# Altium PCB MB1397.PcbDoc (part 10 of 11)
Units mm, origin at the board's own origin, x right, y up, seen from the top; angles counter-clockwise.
Board outline 118.24 x 172.86 mm, 6 copper layers (Top Layer, L2_GND, L3_VCC, L4_SIG, L5_GND, Bottom Layer), stack 1.631 mm thick; 819 components, 632 nets, 2875 pads, 1523 vias.
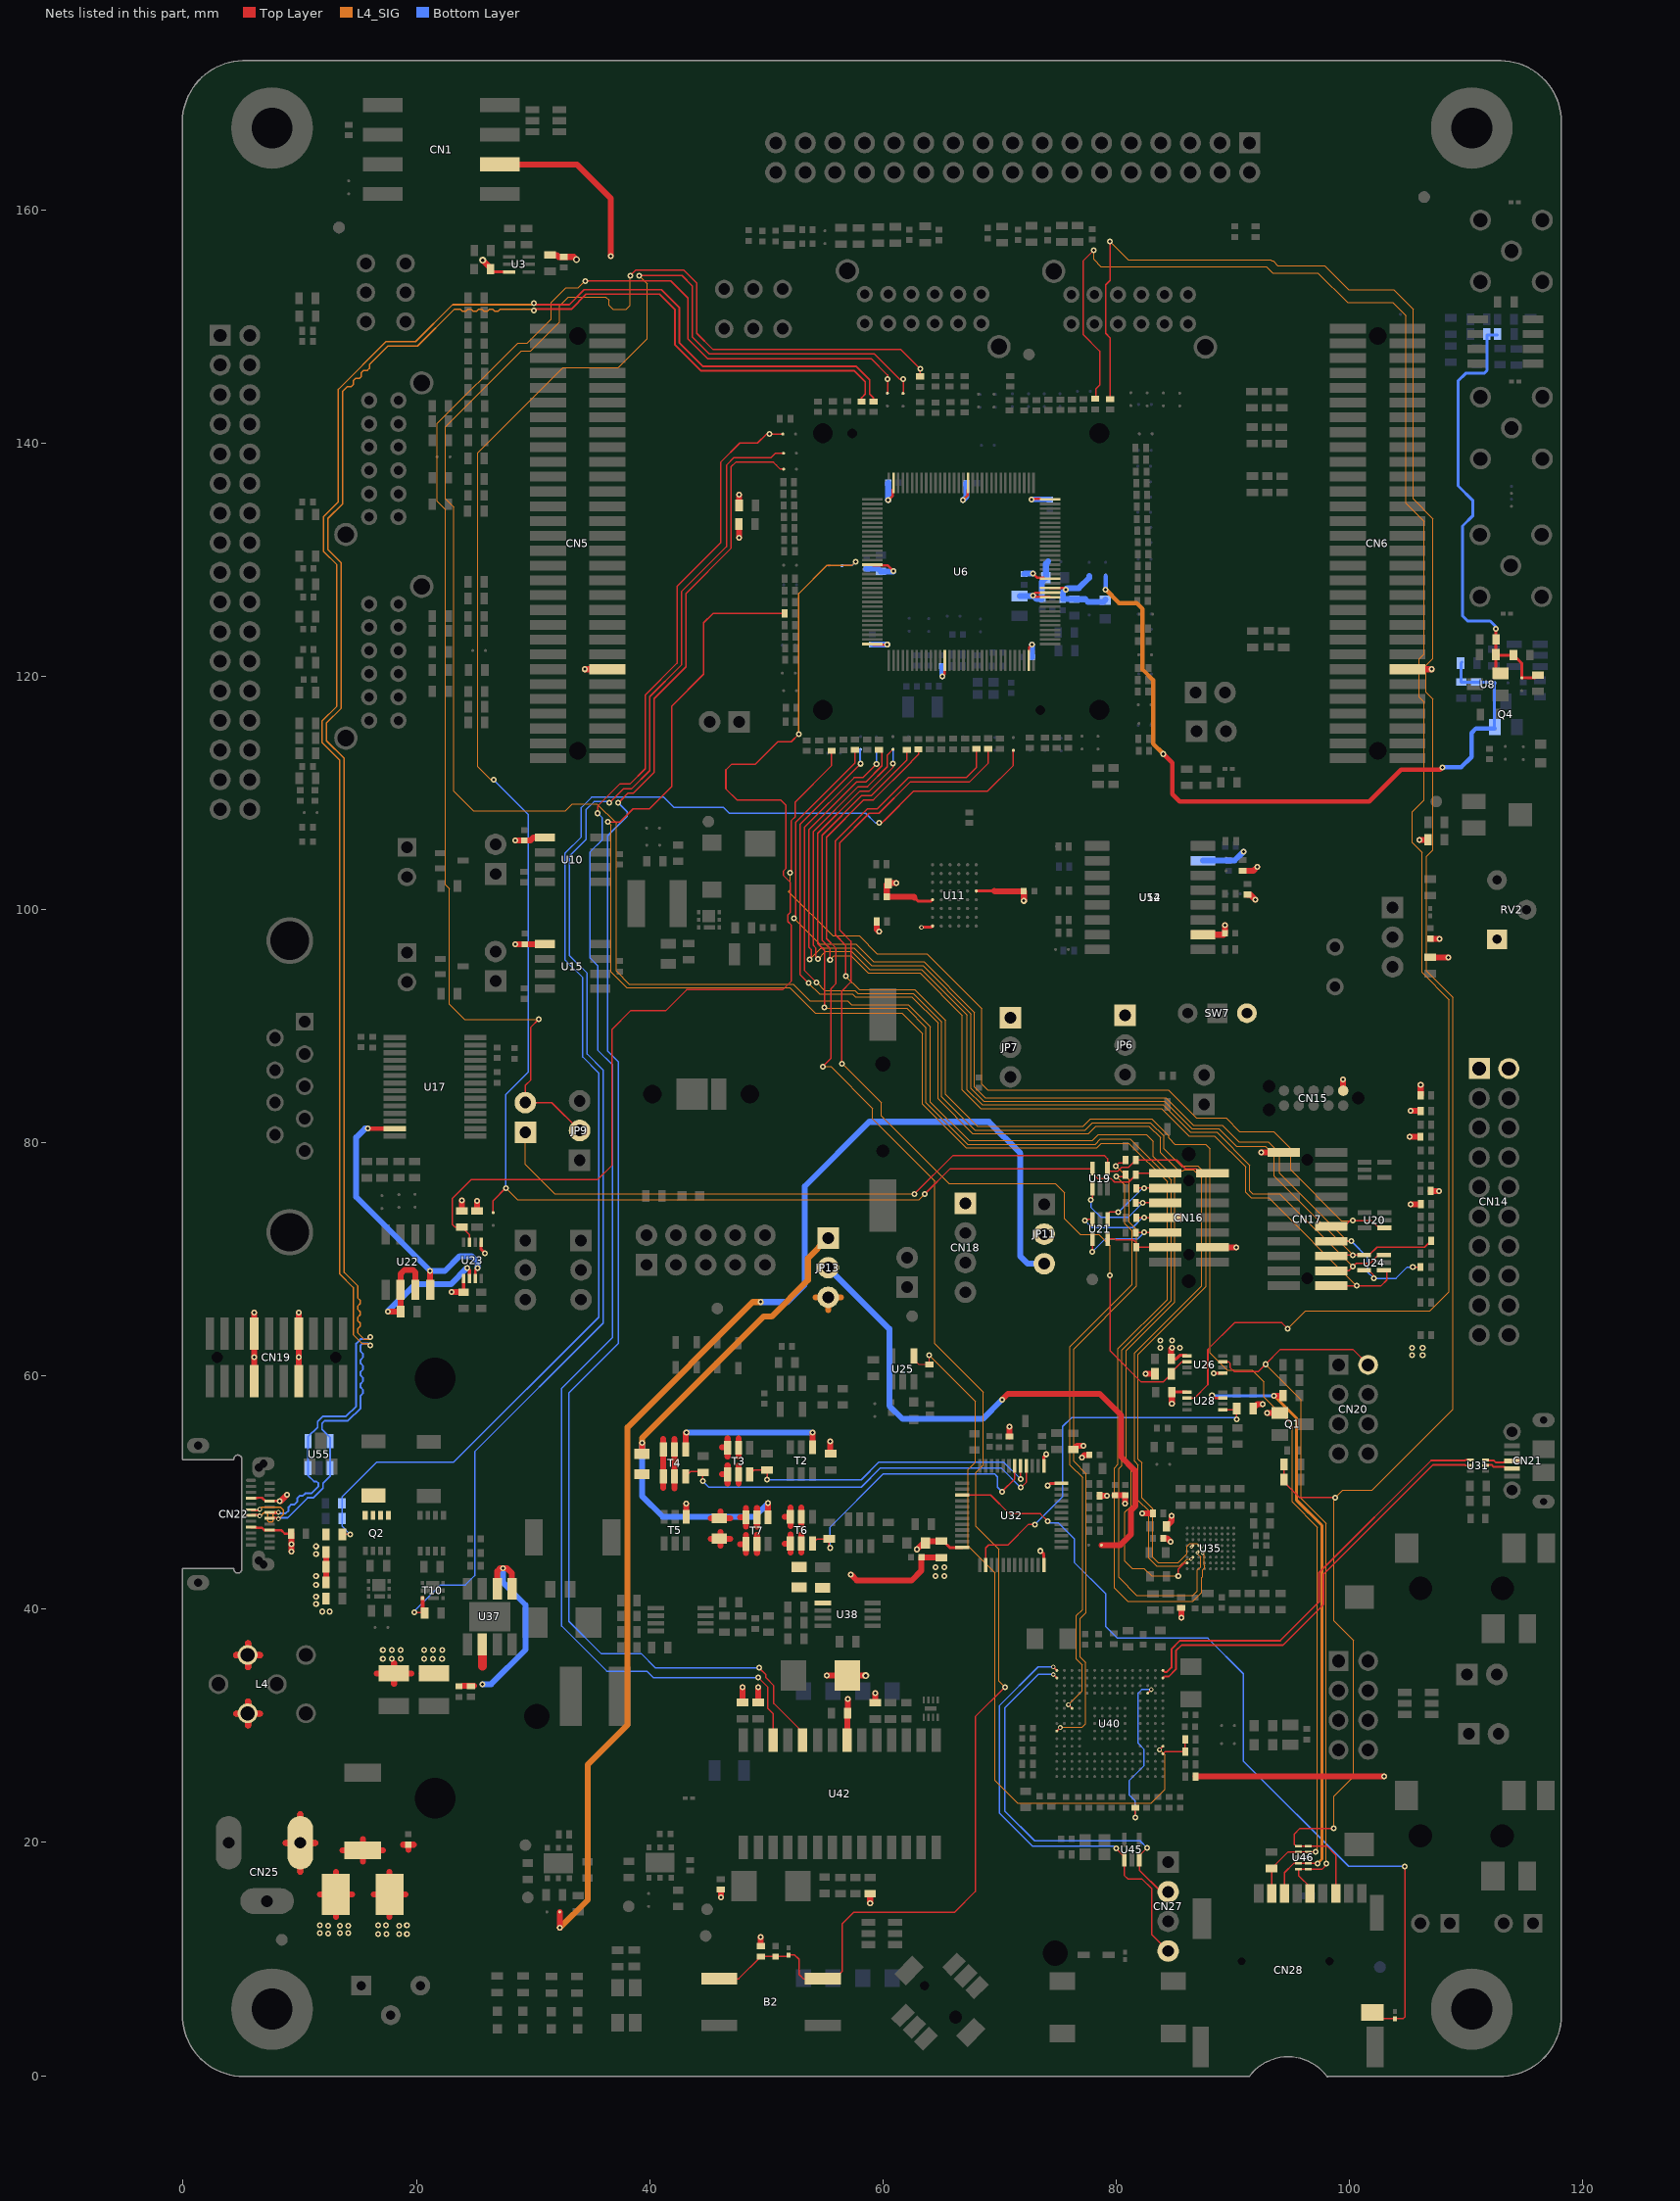
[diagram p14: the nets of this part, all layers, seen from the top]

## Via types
v1: diameter 0.508, hole 0.254, Top Layer to Bottom Layer, tented both sides, 1330 vias
v2: diameter 0.406, hole 0.203, Top Layer to Bottom Layer, tented both sides, 115 vias
v3: diameter 0.508, hole 0.254, Top Layer to Bottom Layer, 33 vias
v4: diameter 0.305, hole 0.152, Top Layer to Bottom Layer, tented both sides, 26 vias
v5: diameter 0.61, hole 0.305, Top Layer to Bottom Layer, tented both sides, 14 vias
v6: diameter 0.61, hole 0.33, Top Layer to Bottom Layer, tented both sides, 2 vias
v7: diameter 0.381, hole 0.203, Top Layer to Bottom Layer, tented both sides, 2 vias
v8: diameter 0.508, hole 0.203, Top Layer to Bottom Layer, tented both sides, 1 vias

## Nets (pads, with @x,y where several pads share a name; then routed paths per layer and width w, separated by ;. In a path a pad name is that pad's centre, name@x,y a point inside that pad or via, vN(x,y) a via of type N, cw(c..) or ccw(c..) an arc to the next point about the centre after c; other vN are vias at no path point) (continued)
RS485_DIR: R201.1 SB123.2 U23.3 | length 98.2
  Top Layer w0.127: U23.3@24.551,71.472 24.551,72.111 R201.1@23.897,72.765 23.312,72.765 23.086,72.991 23.086,75.232 24.689,76.835 35.535,76.835 36.779,78.08 36.779,89.738 38.354,91.313 41.366,91.313 43.17,93.116 51.41,93.116 52.154,93.861 52.154,98.658 51.841,98.971 51.841,99.531 52.07,99.76 52.07,102.311 51.482,102.9 51.482,103.315 51.692,103.525 51.692,108.93 51.224,109.398 47.475,109.398 46.533,110.34 46.533,111.969 47.035,112.471 49.073,112.471 50.978,114.376 52.139,114.376 52.799,115.037 v1(52.781,115.037)
  L4_SIG w0.127: v1(52.781,115.037) 52.781,127.089 55.205,129.513 57.364,129.513 v1(57.661,129.809)
  Bottom Layer w0.127: SB123.2@56.48,129.487 57.339,129.487 v1(57.661,129.809)
RS485_DIR_3V3: R213.2 U22.2 U22.3 U23.6 | length 16.4
  Top Layer w0.254: v1(24.356,69.263) 24.549,69.07 U23.6@24.549,68.656
  Top Layer w0.508: v1(17.546,65.532) R213.2@18.647,65.532 18.636,65.54 18.636,68.75 18.981,69.096 19.698,69.096 19.906,68.887 U22.3@19.907,67.391
  Bottom Layer w0.508: v1(17.546,65.532) 19.883,67.866 22.959,67.866 v1(24.356,69.263)
SAI_FS_A: SB107.1 U35.E3 | length 112.6
  Top Layer w0.127: v1(54.988,91.615) 54.988,96.492 54.399,97.081 54.399,106.523 58.034,110.157 58.834,110.157 60.858,112.179 v1(60.858,112.519) ; v4(86.951,44.84) U35.E3@87.077,44.966
  L4_SIG w0.102: v1(54.988,91.615) 55.077,91.526 62.037,91.526 63.701,89.863 63.701,83.434 67.254,79.88 78.202,79.88 78.633,80.312 81.197,80.312 84.706,76.803 84.706,66.469 80.465,62.227 80.465,52.296 80.236,52.067 80.236,42.72 81.76,41.196 86.586,41.196 86.967,41.577 86.967,43.355 87.236,43.623 87.236,44.486 86.951,44.771 v4(86.951,44.84)
  Bottom Layer w0.127: v1(60.858,112.519) SB107.1@60.858,113.724
SAI_MCLK_A: SB111.1 U35.D3 | length 110
  Top Layer w0.127: v1(54.303,93.749) 53.264,94.788 53.264,107.031 57.534,111.3 58.265,111.3 v1(59.446,112.481) ; U35.D3@87.077,45.466 v4(87.236,45.306)
  L4_SIG w0.102: v1(54.303,93.749) 54.988,93.063 57.579,93.063 57.833,92.809 62.598,92.809 65.047,90.361 65.047,83.944 67.892,81.1 77.34,81.1 77.97,81.73 82.928,81.73 84.097,80.561 84.097,79.499 85.653,77.943 85.71,77.999 86.994,77.999 87.729,77.264 87.729,67.696 81.887,61.854 81.887,52.88 82.192,52.575 82.192,49.546 83.128,48.61 83.128,44.452 83.586,43.993 85.319,43.993 86.078,44.752 86.078,45.391 86.328,45.641 86.898,45.641 v4(87.236,45.306)
  Bottom Layer w0.127: v1(59.446,112.481) 59.461,112.497 SB111.1@59.461,113.698
SAI_SCK_A: R30.1 U35.G1 | length 217.9
  Top Layer w0.127: v1(38.326,154.353) 38.783,154.81 42.949,154.81 44.041,153.718 44.041,149.4 45.438,148.003 61.554,148.003 v1(63.19,146.37) R30.1@63.19,145.713 ; v1(85.316,42.847) 85.316,43.434 85.847,43.965 U35.G1@86.077,43.966
  L4_SIG w0.102: v1(38.326,154.353) 38.326,151.813 37.97,151.458 36.853,151.458 36.497,151.813 36.497,152.245 36.243,152.499 33.017,152.499 32.281,151.762 32.281,150.391 29.792,147.902 29.004,147.902 22.502,141.399 22.502,135.202 23.213,134.49 23.213,110.157 24.889,108.481 32.789,108.481 33.373,109.065 35.481,109.065 37.132,107.414 37.132,94.714 38.25,93.596 52.296,93.596 53.744,92.149 56.97,92.149 57.287,91.831 62.164,91.831 64.072,89.924 64.072,83.495 67.381,80.185 77.95,80.185 78.458,80.693 82.575,80.693 83.157,80.111 83.157,78.831 85.011,76.977 85.011,66.342 80.871,62.202 80.871,52.372 81.277,51.966 81.277,48.842 80.744,48.308 80.744,44.117 81.379,43.482 82.395,43.482 83.03,42.847 v1(85.316,42.847)
SAI_SD_A: R98.2 U35.E4 | length 149.8
  Top Layer w0.127: v1(36.421,107.503) 37.45,107.503 38.58,108.633 39.977,108.633 41.907,110.564 41.907,117.455 44.625,120.172 44.625,124.584 45.415,125.374 R98.2@51.569,125.375 ; v4(87.417,44.806) U35.E4@87.577,44.966
  L4_SIG w0.102: v1(36.421,107.503) 36.421,107.49 36.675,107.236 36.675,94.663 38.047,93.292 52.017,93.292 54.201,91.107 61.646,91.107 63.396,89.357 63.396,83.309 67.13,79.576 78.329,79.576 78.715,79.962 81.069,79.962 84.376,76.655 84.376,66.571 80.16,62.354 80.16,52.423 79.855,52.118 79.855,41.831 80.998,40.688 86.586,40.688 87.348,41.45 87.348,42.72 87.417,42.789 87.417,43.372 87.562,43.517 87.562,43.749 87.541,43.77 87.541,44.612 87.417,44.736 v4(87.417,44.806)
SAI_SD_B: SB110.1 U35.F2 | length 108.2
  Top Layer w0.127: v1(53.617,93.698) 52.885,94.43 52.885,107.29 v1(58.09,112.494) ; v4(86.416,44.305) U35.F2@86.577,44.466
  L4_SIG w0.102: v1(53.617,93.698) 54.557,92.758 57.376,92.758 57.63,92.504 62.471,92.504 64.717,90.259 64.717,83.767 67.688,80.795 77.62,80.795 78.25,81.425 82.801,81.425 83.792,80.434 83.792,79.141 85.339,77.594 85.736,77.594 85.836,77.695 86.633,77.695 87.348,76.98 87.348,67.747 81.557,61.956 81.557,52.702 81.887,52.372 81.887,49.34 82.779,48.448 82.779,44.369 83.459,43.688 85.461,43.688 86.078,44.305 v4(86.416,44.305)
  Bottom Layer w0.127: SB110.1@58.039,113.673 58.039,112.545 v1(58.09,112.494)
SH0: R230.2 T4.3 U32.4 | length 33.4
  Top Layer w0.127: T4.3@43.076,51.389 43.485,51.798 44.549,51.798 v1(44.549,50.975) ; v1(71.816,50.429) 72.306,50.919 U32.4@72.307,52.292
  Bottom Layer w0.127: v1(44.549,50.975) 45.057,50.467 58.138,50.467 59.789,52.118 70.129,52.118 v1(71.816,50.429)
SH0_D: R227.2 T4.1 T4.2 T4.5 T4.6 | length 8.1
  Top Layer w0.508: 41.176,50.424 T4.1@41.176,51.389 T4.6@41.176,53.689 41.176,54.601 ; 42.126,50.38 T4.2@42.126,51.389 42.126,52.349 ; 42.126,52.636 T4.5@42.126,53.689 42.126,54.621
SH1: R229.2 T3.3 U32.5 | length 26.6
  Top Layer w0.127: T3.3@48.58,51.572 48.58,51.57 48.948,51.938 R229.2@50.069,51.94 v1(50.068,51.102) ; v1(71.806,51.151) U32.5@71.807,52.292
  Bottom Layer w0.127: v1(50.068,51.102) 58.138,51.102 59.662,52.626 70.33,52.626 v1(71.806,51.151)
SH1_D: R238.2 T3.1 T3.2 T3.5 T3.6 | length 9.4
  Top Layer w0.508: 45.245,47.785 R238.2@46.073,47.785 ; 46.073,48.39 R238.2@46.073,47.785 ; 46.203,51.57 T3.1@46.68,51.57 ; 46.203,53.871 T3.6@46.68,53.871 ; 46.68,50.792 T3.1@46.68,51.57 ; 46.68,52.349 T3.1@46.68,51.57 ; 46.68,53.094 T3.6@46.68,53.871 ; 46.68,54.648 T3.6@46.68,53.871 ; 46.901,47.785 R238.2@46.073,47.785 ; 47.63,50.792 47.63,52.349 ; 47.63,53.094 47.63,54.648
SH2: R242.2 T6.3 U32.6 | length 24.6
  Top Layer w0.127: T6.3@53.957,45.627 54.366,46.035 R242.2@55.39,46.036 55.39,45.342 v1(55.471,45.26) ; v1(70.203,50.086) 71.305,51.189 U32.6@71.307,52.292
  Bottom Layer w0.127: v1(55.471,45.26) 55.471,47.038 60.043,51.61 69.568,51.61 69.822,51.356 69.822,50.467 v1(70.203,50.086)
SH2_D: R252.2 T6.1 T6.2 T6.5 T6.6 | length 7.2
  Top Layer w0.508: 51.58,45.626 T6.1@52.057,45.627 ; 51.58,47.925 T6.6@52.057,47.927 ; 52.057,44.846 T6.1@52.057,45.627 ; 52.057,46.403 T6.1@52.057,45.627 ; 52.057,47.147 T6.6@52.057,47.927 ; 52.057,48.705 T6.6@52.057,47.927 ; 53.007,44.846 T6.2@53.007,45.627 53.007,46.403 ; 53.007,47.147 T6.5@53.007,47.927 53.007,48.705
SmartCard_CLK: SB15.1 U42.24 | length 137.1
  Top Layer w0.127: v1(37.31,109.141) 38.158,109.99 38.618,109.99 40.383,111.755 40.383,118.087 43.101,120.805 43.101,127.094 46.962,130.955 46.962,137.94 47.374,138.351 50.609,138.351 50.863,138.097 51.199,137.765 SB15.1@51.486,137.765 ; v1(49.375,34.973) 49.947,34.402 49.947,34.148 50.645,33.449 50.645,31.925 53.124,29.446 53.124,28.763 U42.24@53.123,28.765 ; SB15.1@51.486,137.763 SB15.1@51.486,137.763
  Bottom Layer w0.127: v1(37.31,109.141) 38.072,108.379 38.072,107.998 36.396,106.322 36.396,87.856 37.31,86.942 37.31,62.786 33.068,58.544 33.068,38.961 35.829,36.2 39.258,36.2 40.485,34.973 v1(49.375,34.973)
SmartCard_IO: SB12.1 U42.26 | length 138.8
  Top Layer w0.127: v1(35.532,108.252) 35.532,108.862 37.422,110.752 38.301,110.752 39.621,112.07 39.621,118.402 42.339,121.12 42.339,127.699 46.073,131.432 46.073,138.351 47.724,140.002 49.248,140.002 50.01,140.764 v1(50.264,140.764) SB12.1@51.415,140.764 ; v1(49.312,34.148) 50.137,33.322 50.137,31.483 50.584,31.036 50.584,28.763 U42.26@50.583,28.765
  Bottom Layer w0.127: v1(35.532,108.252) 35.938,107.846 35.938,105.992 34.897,104.95 34.897,95.832 35.532,95.197 35.532,87.958 36.802,86.688 36.802,63.294 32.459,58.951 32.459,38.555 36.319,34.694 39.748,34.694 40.295,34.148 v1(49.312,34.148)
SOURCE_EN: R264.2 SB13.1 T10.3 | length 121.9
  Top Layer w0.127: v1(19.842,39.731) R264.2@20.709,39.731 ; v1(36.548,109.141) 37.777,110.371 38.461,110.371 40.002,111.912 40.002,118.245 42.72,120.962 42.72,127.251 46.581,131.112 46.581,138.097 47.216,138.732 50.386,138.732 50.772,139.118 SB13.1@51.474,139.119
  Top Layer w0.305: T10.3@20.533,40.963 20.533,39.906 R264.2@20.709,39.731
  Bottom Layer w0.127: v1(19.842,39.731) 19.842,39.858 22.07,42.085 24.196,42.085 24.991,42.88 24.991,53.515 36.015,64.539 36.015,86.23 34.643,87.602 34.643,94.536 33.119,96.06 33.119,104.569 34.544,105.994 34.544,108.557 35.23,109.243 36.446,109.243 v1(36.548,109.141)
SPI2_MISO: CN28.7 R35.2 R231.1 R233.1 U46.5 U46.6 | length 200.2
  Top Layer w0.127: v1(79.474,157.274) 79.474,153.947 79.093,153.566 79.093,149.4 79.477,149.017 R35.2@79.477,143.675 ; R231.1@94.398,52.426 94.397,50.886 95.705,49.578 v1(98.778,49.578) ; v1(98.651,21.206) 95.755,21.206 95.273,20.724 95.273,19.835 95.41,19.698 98.052,19.698 98.824,18.926 CN28.7@98.824,15.624
  L4_SIG w0.102: v1(79.474,157.274) 81.023,155.725 93.241,155.725 93.342,155.623 93.444,155.623 93.85,155.217 97.889,155.217 99.946,153.159 103.777,153.159 105.458,151.478 105.458,135.202 107.16,133.5 107.16,121.536 106.576,120.952 106.576,118.615 107.16,118.031 107.16,105.103 106.627,104.569 106.627,94.714 108.887,92.453 108.887,57.147 101.953,50.213 99.413,50.213 v1(98.778,49.578) 98.651,49.451 98.651,39.014 100.33,37.335 100.33,25.654 98.651,23.975 v1(98.651,21.206)
SPI2_MOSI: R36.2 U28.2 | length 158.4
  Top Layer w0.127: v1(78.077,156.525) 77.188,155.636 77.188,149.273 78.585,147.876 78.585,144.955 78.247,144.617 R36.2@78.247,143.675 ; U28.2@86.052,58.116 86.716,58.115 87.856,59.256 87.856,62.278 90.142,64.564 94.206,64.564 v1(94.714,64.056)
  L4_SIG w0.102: v1(78.077,156.525) 78.077,155.727 78.689,155.115 92.885,155.115 93.419,154.582 97.3,154.582 99.84,152.042 103.706,152.042 104.823,150.924 104.823,134.846 106.398,133.271 106.398,121.892 105.966,121.46 105.966,118.209 106.398,117.777 106.398,109.395 105.382,108.379 105.382,105.712 106.22,104.874 106.22,94.587 108.557,92.25 108.557,67.231 106.906,65.58 96.238,65.58 v1(94.714,64.056)
SPI2_SCK: R134.2 R218.1 U26.2 | length 85.4
  Top Layer w0.127: v1(56.487,86.789) 56.462,86.815 56.462,92.987 57.249,93.774 57.249,97.279 56.291,98.237 56.291,105.72 58.824,108.252 59.659,108.252 62.326,110.919 67.409,110.919 69.012,112.522 R134.2@69.012,113.774 ; v1(79.474,68.628) 79.474,62.151 82.141,59.484 84.01,59.484 R218.1@84.721,60.194 84.719,60.31 85.644,61.234 U26.2@86.051,61.235
  L4_SIG w0.102: v1(56.487,86.789) 59.847,83.429 59.847,82.319 65.664,76.502 74.775,76.502 75.552,75.725 75.552,73.495 76.916,72.133 78.509,72.133 79.474,71.168 v1(79.474,68.628)
SPI_MOSI_3V3: CN28.3 R220.1 U28.7 U46.2 U46.9 | length 54.1
  Top Layer w0.127: CN28.3@94.423,15.625 94.422,17.409 95.212,18.199 v1(97.254,18.199)
  Top Layer w0.229: v1(88.212,58.341) 88.438,58.115 U28.7@89.152,58.116
  Top Layer w0.508: v1(93.52,58.316) 94.31,58.316 R220.1@94.311,58.318
  L4_SIG w0.254: v1(93.52,58.316) 95.476,56.36 95.476,49.345 97.635,47.186 97.635,18.58 v1(97.254,18.199)
  Bottom Layer w0.254: v1(88.212,58.341) 88.237,58.316 v1(93.52,58.316)
SPI_MOSI_DIR: R222.1 U28.5 U32.26 | length 33.4
  Top Layer w0.127: U32.26@68.806,43.79 68.806,45.26 69.06,45.514 70.711,45.514 72.489,47.292 72.997,47.292 v1(73.022,47.267) ; U28.5@89.152,57.116 90.223,57.114 R222.1@90.331,57.222 v1(90.33,56.284)
  Bottom Layer w0.127: v1(73.022,47.267) 75.41,49.654 75.41,55.674 76.172,56.436 90.178,56.436 v1(90.33,56.284)
SPI_SCK_3V3: CN20.2 CN28.5 U26.7 U46.1 U46.10 | length 64.5
  Top Layer w0.127: U26.7@89.151,61.235 89.611,61.234 89.786,61.059 89.786,60.703 90.117,60.373 92.174,60.373 v1(92.809,61.008) 94.079,62.278 100.279,62.278 CN20.2@101.6,60.96 ; CN28.5@96.623,15.625 96.622,16.175 95.631,17.165 U46.10@95.632,17.699 97.633,17.699 98.016,18.082 v1(98.016,18.209)
  L4_SIG w0.102: v1(92.809,61.008) 95.857,57.96 95.857,49.502 98.016,47.343 v1(98.016,18.209)
STLK_SWCLK: CN27.2 U40.A14 U45.3 | length 33.5
  Top Layer w0.127: v2(74.601,34.405) U40.A14@74.903,34.103 ; v1(82.649,19.53) 81.986,18.867 81.986,17.632 83.844,15.774 CN27.2@84.455,15.774
  Bottom Layer w0.127: v2(74.601,34.405) 73.304,34.404 70.457,31.557 70.457,22.692 73.01,20.14 82.039,20.14 v1(82.649,19.53)
STLK_SWDIO: CN27.4 U40.A15 U45.1 | length 38.2
  Top Layer w0.127: v2(74.601,35.055) U40.A15@74.903,34.753 ; v1(80.007,19.479) 80.686,18.801 80.686,17.186 80.981,16.891 82.192,16.891 83.058,16.025 83.058,12.091 CN27.4@84.455,10.694
  Bottom Layer w0.127: v2(74.601,35.055) 73.307,35.055 70,31.747 70,22.502 72.819,19.682 79.804,19.682 v1(80.007,19.479)
STLK_VCP_RX: R194.2 U40.C10 | length 50.7
  Top Layer w0.127: v2(75.901,31.805) U40.C10@76.203,31.503 ; v1(80.01,77.102) 80.642,77.102 R194.2@80.8,77.261
  L4_SIG w0.102: v2@75.9,31.806 77.086,32.992 77.086,35.227 76.578,35.735 76.578,39.444 77.112,39.977 77.112,51.305 76.045,52.372 76.045,62.532 81.379,67.866 81.379,72.438 80.744,73.073 80.744,76.37 v1(80.01,77.102)
STLK_VCP_TX: R189.1 U40.A7 | length 55.5
  Top Layer w0.127: U40.A7@74.905,29.554 v2(75.207,29.856) ; v1(79.967,78.006) 80.241,78.28 80.551,78.28 R189.1@80.797,78.527
  L4_SIG w0.102: v2@75.202,29.848 75.209,29.855 75.245,29.893 77.086,29.893 77.391,30.198 77.391,35.43 76.909,35.913 76.909,39.218 77.417,39.726 77.417,51.61 76.35,52.677 76.35,62.304 81.76,67.714 81.76,72.565 81.125,73.2 81.125,76.848 v1(79.967,78.006)
T50_4: JP13.1 R227.1 T7.4 | length 43.3
  Top Layer w0.508: R227.1@39.342,53.376 v1(39.342,54.277) ; T7.4@50.15,47.887 v1(50.15,49.083)
  L4_SIG w0.508: v1(39.342,54.277) 39.342,54.68 49.76,65.098 50.442,65.098 53.566,68.222 53.566,70.086 JP13.1@55.304,71.826
  Bottom Layer w0.508: v1(39.342,54.277) 39.342,49.705 41.12,47.927 48.994,47.927 v1(50.15,49.083)
T50_6: R238.1 R252.1 R253.1 T7.1 T7.2 T7.5 T7.6 U38.5 | length 10
  Top Layer w0.508: 45.245,46.038 R238.1@46.073,46.038 ; 46.073,45.433 R238.1@46.073,46.038 ; 46.073,46.639 R238.1@46.073,46.038 ; 46.901,46.038 R238.1@46.073,46.038 ; 47.772,45.585 T7.1@48.25,45.585 ; 47.772,47.887 T7.6@48.25,47.887 ; 48.25,44.808 T7.1@48.25,45.585 ; 48.25,46.365 T7.1@48.25,45.585 ; 48.25,47.107 T7.6@48.25,47.887 ; 48.25,48.664 T7.6@48.25,47.887 ; 49.2,44.808 T7.2@49.2,45.585 49.2,46.365 ; 49.2,47.107 T7.5@49.2,47.885 49.2,48.664
T_JTDI_STDC: CN16.10 R199.1 U19.1 | length 9.5
  Top Layer w0.127: v1(77.823,75.095) 77.823,75.105 77.955,75.237 U19.1@77.956,76.077 ; R199.1@81.684,74.847 v1(82.268,74.846) CN16.10@84.194,74.847
  Bottom Layer w0.127: v1(77.823,75.095) 77.823,74.47 78.674,73.619 81.041,73.619 v1(82.268,74.846)
T_NRST_STDC: CN16.12 R196.1 U21.1 | length 7
  Top Layer w0.127: U21.1@79.263,73.446 79.263,73.878 79.449,74.064 v1(80.185,74.064) ; R196.1@81.723,76.077 81.763,76.116 v1(82.395,76.116) CN16.12@84.194,76.117
  Bottom Layer w0.127: v1(80.185,74.064) 80.211,74.064 82.263,76.116 v1(82.395,76.116)
T_PWR_EN: R217.2 U25.4 U40.R5 | length 61.7
  Top Layer w0.102: U25.4@62.649,61.682 62.649,61.412 63.068,60.993 R217.2@63.98,60.993 63.98,61.755 v1(63.965,61.77)
  Top Layer w0.127: v2(83.702,27.949) U40.R5@84.005,28.251
  L4_SIG w0.102: v1(63.965,61.77) 67.917,57.818 67.917,52.626 67.282,51.991 67.282,45.438 69.619,43.101 69.619,25.321 71.549,23.391 83.005,23.391 84.173,24.559 84.173,27.48 v2@83.703,27.95
T_PWR_EXT: R277.1 R279.2 U40.R4 | length 3.1
  Top Layer w0.127: U40.R4@84.005,27.602 84.181,27.777 R279.2@85.921,27.778 R277.1@85.921,28.851
T_SWCLK_STDC: CN16.6 R206.1 U21.4 | length 8.7
  Top Layer w0.127: v1(77.955,70.655) 77.963,70.66 U21.4@77.963,71.746 ; R206.1@81.7,72.286 81.719,72.306 v1(82.395,72.306) CN16.6@84.194,72.307
  Bottom Layer w0.127: v1(77.955,70.655) 79.047,71.745 81.834,71.745 v1(82.395,72.306)
T_SWDIO_IN: R285.1 U40.N12 | length 14.2
  Top Layer w0.127: v1(81.636,22.146) R285.1@81.636,22.999 ; U40.N12@82.705,32.803 U40.N12@82.747,32.845 ; U40.N12@82.705,32.803 v2(83.007,33.106)
  Bottom Layer w0.127: v1(81.636,22.146) 81.636,23.541 81.125,24.051 81.125,25.321 82.395,26.591 82.395,27.988 81.887,28.496 81.887,32.814 82.179,33.106 v2(83.007,33.106)
T_SWDIO_STDC: CN16.4 R208.1 U21.5 | length 5.5
  Top Layer w0.127: U21.5@79.263,71.746 79.913,71.746 79.98,71.679 81.458,71.679 81.73,71.407 R208.1@81.73,71.036 ; R208.1@81.705,71.029 81.713,71.037 CN16.4@84.194,71.037
T_SWO_STDC: CN16.8 R204.1 U21.3 | length 8.8
  Top Layer w0.127: v1(77.315,73.327) 77.432,73.444 U21.3@77.963,73.446 ; R204.1@81.723,73.577 v1(82.395,73.576) CN16.8@84.194,73.577
  Bottom Layer w0.127: v1(77.315,73.327) 77.912,72.73 81.417,72.73 82.263,73.576 v1(82.395,73.576)
TAMPER_KEY: B2.1 B2.2 C157.2 R141.1 R294.1 U50.1 | length 140.8
  Top Layer w0.127: B2.1@45.964,8.318 47.63,8.316 R294.1@49.53,10.218 51.775,10.216 51.911,10.354 U50.1@51.914,10.356 ; U50.1@51.913,10.353 U50.1@51.914,10.356 ; v1(54.836,86.535) 55.535,87.234 55.535,93.203 55.979,93.647 55.979,96.685 55.156,97.508 55.156,106.202 58.349,109.395 59.185,109.395 62.433,112.644 62.433,112.674 63.043,113.284 R141.1@63.043,113.717 ; v1(70.457,33.322) 67.917,30.782 67.917,15.796 66.139,14.018 57.503,14.018 56.487,13.002 56.487,8.938 55.865,8.316 53.172,8.316 52.804,8.684 52.804,9.975 52.423,10.356 U50.1@51.914,10.356
  L4_SIG w0.102: v1(54.836,86.535) 55.522,86.535 59.129,82.928 59.129,82.045 64.463,76.711 64.463,62.761 68.603,58.621 68.603,52.372 67.968,51.737 67.968,47.114 69.949,45.133 69.949,33.83 v1(70.457,33.322)
TRACECLK: CN17.12 R147.1 U20.1 | length 84.1
  Top Layer w0.127: v1(52.051,103.147) 52.051,103.031 52.128,103.109 52.128,107.603 52.469,107.943 52.469,109.205 55.601,112.337 R147.1@55.601,113.621 ; CN17.12@98.428,72.823 99.543,72.822 100.048,73.327 v1(100.302,73.327) 101.882,73.327 102.502,72.708 U20.1@103.243,72.708
  L4_SIG w0.102: v1(52.051,103.147) 52.051,101.708 51.89,101.547 55.7,97.737 57.96,97.737 59.484,96.213 63.778,96.213 68.476,91.514 68.476,85.011 68.969,84.519 84.463,84.519 86.865,82.116 89.431,82.116 90.574,80.973 93.499,80.973 94.971,79.501 94.971,77.673 99.317,73.327 v1(100.302,73.327)
TRACED0: CN17.14 R145.1 R210.1 U24.5 | length 91.8
  Top Layer w0.127: v1(52.372,99.235) 52.507,99.37 52.507,107.446 57.607,112.547 R145.1@57.607,113.672 ; CN17.14@98.428,71.553 v1(100.173,71.552) ; U24.5@101.511,69.068 101.641,69.068 102.08,68.628 v1(102.08,68.374) ; v1(105.43,69.342) R210.1@106.091,69.342
  L4_SIG w0.102: v1(52.372,99.235) 54.582,97.025 57.681,97.025 59.187,95.519 63.508,95.519 67.854,91.173 67.854,84.77 68.76,83.863 84.254,83.863 86.611,81.506 89.101,81.506 90.523,80.084 93.038,80.084 94.005,79.116 94.005,77.385 99.839,71.552 v1(100.173,71.552)
  Bottom Layer w0.127: v1(100.173,71.552) 101.572,70.152 101.572,68.882 v1(102.08,68.374) 103.985,68.374 104.953,69.342 v1(105.43,69.342)
TRACED1: CN17.16 R144.1 R207.1 U24.4 | length 93.1
  Top Layer w0.127: v1(53.718,95.73) 53.851,95.862 53.851,96.56 53.642,96.768 53.642,106.843 57.719,110.919 58.519,110.919 59.916,112.316 59.916,113.429 R144.1@59.665,113.681 ; CN17.16@98.428,70.283 98.514,70.368 v1(100.302,70.368) 101.684,70.368 102.357,71.041 106.441,71.041 R207.1@106.991,71.59
  L4_SIG w0.102: v1(53.718,95.73) 54.684,96.695 57.503,96.695 59.027,95.171 63.424,95.171 67.549,91.046 67.549,84.643 68.633,83.558 84.127,83.558 86.487,81.201 88.796,81.201 90.294,79.703 92.784,79.703 93.548,78.938 93.548,77.122 v1(100.302,70.368)
TRACED2: CN17.18 SB28.1 U24.3 | length 89.1
  Top Layer w0.127: v1(54.43,95.755) 54.229,95.956 54.229,96.716 54.021,96.925 54.021,106.683 57.876,110.538 58.677,110.538 60.373,112.235 60.373,113.238 SB28.1@60.858,113.724 ; CN17.18@98.428,69.013 99.924,69.012 v1(100.289,69.378) 100.556,69.644 101.754,69.644 102.478,70.368 U24.3@103.21,70.368
  L4_SIG w0.102: v1(54.43,95.755) 55.065,96.39 57.325,96.39 58.849,94.866 63.297,94.866 67.231,90.932 67.231,84.529 68.506,83.254 84.003,83.254 86.36,80.896 88.638,80.896 91.463,78.072 91.463,75.888 91.712,75.639 94.028,75.639 v1(100.289,69.378)
TRACED3: CN17.20 R142.1 U24.1 | length 89.7
  Top Layer w0.127: v1(55.458,95.692) 55.458,96.665 54.778,97.346 54.778,106.363 58.191,109.776 59.027,109.776 62.052,112.801 R142.1@62.052,113.705 ; CN17.20@98.428,67.743 v1(100.607,67.742) 102.718,67.742 103.21,68.237 U24.1@103.21,69.068
  L4_SIG w0.102: v1(55.458,95.692) 55.801,96.035 57.249,96.035 58.722,94.562 63.17,94.562 66.807,90.925 66.807,84.522 68.38,82.949 83.876,82.949 86.233,80.592 88.44,80.592 91.107,77.925 91.107,75.74 91.564,75.283 93.066,75.283 v1(100.607,67.742)
USART1_RX: JP9.2 JP10.2 SB3.1 | length 123.1
  Top Layer w0.127: v1(30.477,90.574) 29.817,89.913 29.817,85.392 29.337,84.912 JP10.2@29.337,83.439 31.605,83.439 JP9.2@33.995,81.05 ; v1(34.465,153.896) 41.806,153.896 43.279,152.423 43.279,148.923 44.961,147.241 58.976,147.241 60.394,145.824 v1(60.394,145.479) SB3.1@60.394,144.247
  L4_SIG w0.102: v1(30.477,90.574) 24.127,90.574 22.832,91.869 22.832,101.775 22.502,102.105 22.502,134.287 21.791,134.998 21.791,141.679 28.694,148.582 29.505,148.582 31.57,150.645 31.57,152.042 32.828,153.3 33.869,153.3 v1(34.465,153.896)
USART1_TX: CN16.14 R194.1 SB4.1 SB40.1 U19.5 | length 181.8
  Top Layer w0.127: SB40.1@26.579,74.012 26.579,75.042 v1(27.658,76.121) ; v1(39.088,154.353) 42.771,154.353 43.66,153.464 43.66,149.08 45.118,147.622 59.281,147.622 61.438,145.466 v1(61.74,145.466) SB4.1@61.74,144.234 ; v1(63.599,75.613) 65.763,77.777 U19.5@77.956,77.777 77.955,77.386 78.407,76.934 79.55,76.934 79.855,76.629 81.069,76.629 81.826,77.386 CN16.14@84.194,77.387
  L4_SIG w0.102: v1(26.612,111.122) 26.388,111.122 25.27,112.24 25.27,139.164 32.586,146.479 37.31,146.479 39.774,148.943 39.774,153.667 v1(39.088,154.353) ; v1(27.658,76.121) 28.674,75.105 63.091,75.105 v1(63.599,75.613)
  Bottom Layer w0.127: v1(26.612,111.122) 29.588,108.146 29.588,86.053 27.658,84.122 v1(27.658,76.121)
USART1_TX_3V3: U17.13 U22.4 U23.7 | length 25.6
  Top Layer w0.229: U23.7@25.051,68.372 25.049,69.068 v1(25.245,69.263)
  Top Layer w0.381: v1(15.847,81.211) U17.13@18.14,81.213
  Top Layer w0.508: U22.4@21.177,67.391 v1(21.176,69.004)
  Bottom Layer w0.508: v1(15.847,81.211) 15.593,81.211 14.831,80.449 14.831,75.352 v1(21.176,69.004) 22.446,69.004 23.721,70.279 24.737,70.279 25.245,69.771 v1(25.245,69.263)
USB_DEV_HS_CN_N: CN21.2 U31.5 | length 2.4
  Top Layer w0.155: U31.5@111.654,52.316 U31.5@111.654,52.316 111.722,52.382 112.197,52.382 112.377,52.205 113.297,52.205 113.431,52.07 CN21.2@113.938,52.071
USB_DEV_HS_CN_P: CN21.3 U31.6 | length 2.4
  Top Layer w0.155: U31.6@111.654,52.816 111.704,52.763 112.357,52.763 112.535,52.586 113.215,52.586 113.35,52.72 CN21.3@113.938,52.721
USB_DEV_HS_N: U31.2 U40.R14 | length 36.4
  Top Layer w0.155: U40.R14@84.005,34.103 84.139,34.237 84.511,34.237 85.115,34.841 85.115,36.423 85.614,36.922 94.286,36.922 97.765,40.4 97.765,42.977 107.163,52.376 109.917,52.376 109.976,52.316 U31.2@110.354,52.316
USB_DEV_HS_P: U31.1 U40.R15 | length 36.3
  Top Layer w0.155: U40.R15@84.005,34.753 84.139,34.618 84.353,34.618 84.734,34.999 84.734,36.581 85.456,37.303 94.068,37.303 97.384,40.619 97.384,43.135 107.006,52.757 109.917,52.757 109.976,52.816 U31.1@110.354,52.816
USB_DM: CN22.A7 CN22.B7 R46.1 U55.3 U55.4 | length 168.3
  Top Layer w0.155: CN22.B7@5.814,48.532 CN22.B7@5.816,48.534 5.875,48.473 6.477,48.473 v2(6.566,48.562) ; CN22.A7@7.414,47.782 7.475,47.843 8.077,47.843 v2(8.166,47.755) ; v1(30.071,152.004) 30.211,151.864 33.111,151.864 34.394,153.147 40.993,153.147 42.55,151.59 42.55,148.575 44.541,146.583 57.689,146.583 58.864,145.408 58.864,144.198 59.181,143.882 R46.1@59.181,143.549
  L4_SIG w0.13: v2(6.566,48.562) 6.744,48.74 8.359,48.74 8.588,48.511 8.588,48.136 8.207,47.755 v2(8.166,47.755) ; v1@16.038,62.647 15.898,62.786 15.339,62.786 14.577,63.548 14.577,67.582 13.434,68.725 13.434,112.794 11.91,114.318 11.91,116.157 13.18,117.427 13.18,129.558 12.037,130.701 12.037,133.683 13.307,134.953 13.307,144.605 17.391,148.689 19.931,148.689 23.106,151.864 29.931,151.864 v1(30.071,152.004)
  Bottom Layer w0.155: v2(8.166,47.755) 8.255,47.843 8.956,47.843 10.668,49.555 11.156,49.555 11.986,50.386 11.986,50.797 12.606,51.417 12.606,54.724 11.91,55.42 11.91,55.931 12.139,56.159 14.128,56.159 15.212,57.244 15.212,58.308 15.415,58.511 15.415,58.821 15.212,59.025 15.212,59.334 15.415,59.538 15.415,59.847 15.212,60.051 15.212,60.361 15.415,60.564 15.415,60.874 15.212,61.077 15.212,61.387 15.415,61.59 15.415,61.9 15.212,62.103 15.212,62.629 15.37,62.786 15.872,62.786 v1(16.038,62.621)
USB_DP: CN22.A6 CN22.B6 R45.1 U55.1 U55.6 | length 168.6
  Top Layer w0.155: CN22.B6@5.814,48.034 CN22.B6@5.816,48.034 5.875,48.092 6.477,48.092 v2(6.566,48.003) ; CN22.A6@7.415,48.282 7.475,48.224 8.077,48.224 v2(8.166,48.313) ; v1(30.071,151.343) 30.211,151.483 33.269,151.483 34.552,152.766 40.836,152.766 42.169,151.432 42.169,148.417 44.383,146.202 57.531,146.202 58.483,145.25 58.483,144.198 58.166,143.882 R45.1@58.166,143.549
  L4_SIG w0.13: v2(6.566,48.003) 6.652,48.003 6.949,48.301 7.107,48.301 7.236,48.171 7.236,47.6 7.366,47.47 7.617,47.47 7.722,47.574 7.722,48.209 7.871,48.359 8.12,48.359 v2(8.166,48.313) ; v1@16.038,63.307 15.898,63.167 15.497,63.167 14.958,63.706 14.958,64.038 15.187,64.267 15.187,64.526 14.958,64.755 14.958,65.014 15.187,65.242 15.187,65.502 14.958,65.73 14.958,65.989 15.187,66.218 15.187,66.477 14.958,66.705 14.958,67.739 13.815,68.882 13.815,112.951 12.291,114.475 12.291,115.999 13.561,117.269 13.561,129.715 12.418,130.858 12.418,133.525 13.688,134.795 13.688,144.447 14.074,144.833 14.404,144.833 14.587,145.016 14.587,145.346 14.77,145.532 15.1,145.532 15.286,145.715 15.286,146.045 15.469,146.228 15.799,146.228 15.982,146.411 15.982,146.741 17.549,148.308 20.089,148.308 23.264,151.483 23.757,151.483 23.96,151.28 24.219,151.28 24.422,151.483 24.681,151.483 24.884,151.28 25.143,151.28 25.347,151.483 25.606,151.483 25.809,151.28 26.068,151.28 26.271,151.483 26.53,151.483 26.733,151.28 26.993,151.28 27.196,151.483 29.931,151.483 v1(30.071,151.343)
  Bottom Layer w0.155: v2(8.166,48.313) 8.255,48.224 8.796,48.224 9.035,48.463 9.035,48.76 9.256,48.981 9.549,48.981 9.774,49.203 9.774,49.5 9.992,49.718 10.246,49.718 10.465,49.936 10.998,49.936 11.605,50.543 11.605,50.795 11.45,50.95 11.224,50.95 10.706,51.468 U55.1@10.706,54.724 ; U55.1@10.706,54.411 10.706,54.778 11.529,55.601 11.529,56.089 11.981,56.54 13.97,56.54 14.831,57.401 14.831,62.787 15.212,63.167 15.872,63.167 v1(16.038,63.332)
uSD_CS: CN28.2 R135.2 R287.1 U46.4 U46.7 | length 141.9
  Top Layer w0.127: v1(56.805,94.282) 56.805,96.937 55.913,97.828 55.913,105.88 58.666,108.633 59.501,108.633 62.168,111.3 67.13,111.3 68.016,112.187 R135.2@68.016,113.765 ; CN28.2@93.323,15.625 R287.1@93.323,17.776 94.745,19.197 v1(97.099,19.197)
  L4_SIG w0.102: v1(56.805,94.282) 57.973,93.114 62.725,93.114 65.352,90.488 65.352,84.148 68.095,81.404 77.163,81.404 77.793,82.034 83.053,82.034 84.529,80.559 84.529,80.388 85.037,79.88 87.653,79.88 88.034,79.499 88.034,61.973 89.507,60.5 91.666,60.5 92.682,59.484 92.682,58.214 95.095,55.801 95.095,49.187 97.254,47.028 97.254,19.352 v1(97.099,19.197)
uSD_Detect: CN28.10 U32.15 U52.1 | length 74.3
  Top Layer w0.127: U32.15@66.807,49.792 69.228,49.792 70.838,48.181 73.505,48.181 v1(74.14,47.546) ; CN28.10@101.973,5.425 102.502,4.895 U52.1@103.886,4.895 ; U52.1@103.886,4.892 U52.1@103.886,4.895 ; v1(104.747,17.955) 104.747,5.039 104.6,4.895 U52.1@103.886,4.895
  Bottom Layer w0.127: v1(74.14,47.546) 74.267,47.419 75.029,47.419 76.426,46.022 76.426,43.99 79.093,41.323 79.093,38.529 80.109,37.513 87.856,37.513 90.904,34.465 90.904,26.972 99.921,17.955 v1(104.747,17.955)
VBUS: CN19.7 CN19.8 CN19.13 CN19.14 CN22.A4 CN22.A9 CN22.B4 CN22.B9 D8.1 Q2.5 Q2.6 Q2.7 Q2.8 R244.2 R246.2 R250.2 R254.2 R259.2 U36.1 | length 23
  Top Layer w0.203: CN22.B4@5.814,47.033 6.251,47.033 6.286,46.998 6.744,46.998 6.957,46.782 7.414,46.782 7.417,46.784 8.411,46.784 8.713,46.482 U36.1@9.281,46.482 ; CN22.B9@5.816,49.534 6.358,49.533 6.388,49.563 6.746,49.563 6.774,49.533 6.784,49.533 6.888,49.428 6.916,49.428 7.061,49.284 v1(8.268,49.284) v1@8.377,49.284
  Top Layer w0.508: CN19.7@6.096,59.56 CN19.7@6.096,59.56 v1(6.096,61.615) CN19.8@6.096,63.63 v1(6.096,65.453) ; v1@8.377,49.284 v1(8.9,49.807) ; v1(9.281,44.955) v1(9.281,45.593) U36.1@9.281,46.482 ; CN19.13@9.906,59.56 CN19.13@9.906,59.56 v1(9.906,61.615) CN19.14@9.906,63.63 v1(9.906,65.453) ; R254.2@12.254,42.306 R250.2@12.254,43.634 R246.2@12.254,44.904
  other v1: 11.91,39.799 12.545,39.799 11.402,40.434 11.402,41.069 11.402,42.085 11.402,42.847 11.402,44.752 11.402,45.387
VCP_RX_STDC: CN16.13 JP10.1 R189.2 U19.4 | length 66
  Top Layer w0.127: v1(62.71,75.613) 66.012,78.915 78.966,78.915 79.256,78.626 U19.4@79.256,77.777 79.484,77.546 80.137,77.546 80.49,77.899 81.069,77.899 R189.2@81.697,78.527 85.197,78.527 85.951,77.772 86.84,77.772 87.226,77.386 CN16.13@88.258,77.387
  L4_SIG w0.102: JP10.1@29.337,80.899 29.337,78.125 31.849,75.613 v1(62.71,75.613)
VDD: C13.1 C40.1 C46.2 C47.1 C48.1 C50.1 C51.2 C52.1 C61.1 C64.1 C69.1 C75.2 C80.2 C82.1 C83.2 C92.2 C94.1 C98.2 C121.1 C127.2 C184.2 CN1.5 CN5.48 CN6.48 CN14.1 CN14.2 CN15.1 CN16.3 CN17.1 CN18.1 JP7.1 JP11.2 Q1.1 R14.2 R16.2 R73.2 R80.2 R158.2 R161.1 R166.1 R171.2 R179.2 R183.2 R184.2 R186.2 R197.2 R200.2 R201.2 R202.2 R218.2 R222.2 R225.2 R228.2 R235.1 R237.1 R245.2 R261.1 R273.2 R274.2 R275.2 R282.2 R290.2 R291.2 R294.2 RV2.1 SW7.2 T5.4 U3.3 U10.5 U11.A6 U11.D6 U11.E1 U12.2 U15.5 U23.1 U23.5 U26.1 U26.5 U28.1 U35.D2 U42.21 U54.2 | length 128.2
  Top Layer w0.229: v4(86.451,45.34) 86.452,45.34 U35.D2@86.577,45.466
  Top Layer w0.254: U23.1@25.551,71.472 25.55,70.863 v1(25.88,70.533) ; C13.1@26.351,154.897 26.577,154.671 U3.3@27.932,154.671 ; 62.71,101.013 63.015,100.708 64.125,100.708 U11.D6@64.249,100.835 U11.D6@64.249,100.835 ; v2(63.294,98.473) 64.14,98.473 U11.A6@64.249,98.585 ; U11.E1@67.999,101.585 68.026,101.613 69.555,101.613 ; C64.1@84.721,61.464 85.136,61.463 85.443,61.77 86.015,61.77 U26.1@86.051,61.735 ; C69.1@84.771,58.619 86.048,58.618 U28.1@86.052,58.616 U28.1@86.052,58.616 ; U28.1@86.052,58.616 U28.1@86.053,58.616 ; v1(88.364,60.234) U26.5@89.151,60.235
  Top Layer w0.305: C61.1@24.039,67.187 24.051,67.198 U23.5@24.051,68.123
  Top Layer w0.508: v1(23.005,67.186) C61.1@24.039,67.187 ; R201.2@23.896,74.165 v1(23.896,75.057) ; R202.2@25.199,74.165 v1(25.199,75.024) ; v5(25.679,155.677) 26.351,155.005 C13.1@26.351,154.897 ; CN1.5@27.135,163.889 33.744,163.888 36.675,160.957 v1(36.675,156.004) ; v1(28.473,105.913) 29.764,105.913 30.02,106.169 U10.5@31.011,106.171 ; v1(28.478,97.008) 29.309,97.008 29.329,97.028 U15.5@31.011,97.029 ; R14.2@31.445,156.123 32.03,156.123 32.193,155.96 R16.2@32.639,155.96 33.491,155.96 v5(33.723,155.727) ; v1(34.44,120.599) CN5.48@36.385,120.601 ; T5.4@43.134,47.912 v1(43.134,49.07) ; v1(46.104,15.288) R291.2@46.103,15.952 ; v1(47.658,131.874) R80.2@47.658,133.144 ; R73.2@47.658,134.668 v1(47.658,135.557) ; R273.2@47.974,32.012 v1(47.973,33.317) ; R274.2@49.313,32.012 49.314,32.012 v1(49.314,33.322) ; R294.2@49.53,11.118 v1(49.53,11.887) ; v1(55.178,34.313) C121.1@56.936,34.313 v5(58.529,34.313) ; R228.2@55.491,53.327 v1(55.491,54.384) ; U42.21@56.933,28.765 56.934,28.763 56.934,31.044 C127.2@56.975,31.087 ; v1(56.975,32.306) C127.2@56.975,31.087 ; C127.2@56.977,31.088 C127.2@56.975,31.087 ; v1(57.249,42.974) 57.757,42.466 62.456,42.466 63.307,43.317 C98.2@63.308,44.455 R245.2@64.976,44.455 ; v1(58.9,14.808) R290.2@58.9,15.599 R290.2@58.9,15.603 ; R275.2@59.336,31.987 v1(59.337,32.814) ; R171.2@59.467,98.982 59.466,98.288 v1(59.662,98.092) ; C48.1@60.326,101.088 C48.1@60.328,101.087 ; C46.2@60.455,102.255 C46.2@60.455,102.258 ; C46.2@60.457,102.256 C46.2@60.328,102.126 ; v1(61.161,102.258) C46.2@60.455,102.258 ; 62.71,101.013 62.636,101.087 C48.1@60.328,101.087 ; 69.555,101.613 69.596,101.572 72.085,101.572 v1(72.085,100.736) ; R225.2@70.845,54.803 v1(70.846,55.667) ; C75.2@76.313,53.695 76.642,54.023 v1(77.188,54.023) ; v1(77.061,53.007) 77.29,53.236 C80.2@77.679,53.238 ; R235.1@78.588,49.725 78.588,49.726 v1(79.2,49.726) ; C82.1@79.855,49.764 80.744,49.764 v1(80.744,49.07) ; v1(82.245,48.205) 83.128,48.205 R237.1@83.147,48.225 ; v1(82.522,60.193) R218.2@83.321,60.194 ; C94.1@84.047,46.077 84.379,46.076 v1(84.658,45.796) ; C92.2@84.297,47.119 84.757,47.579 v1(84.757,48.003) ; C64.1@84.721,61.464 84.719,62.316 v1(84.808,62.405) ; v1(84.77,57.643) C69.1@84.771,58.619 ; v1(85.57,39.291) R261.1@85.57,40.112 ; R282.2@86.821,25.656 v1(102.969,25.654) ; U12.2@87.454,97.839 89.182,97.838 C51.2@89.312,97.966 v1(89.311,98.671) ; CN16.3@88.258,71.037 90.273,71.037 v1(90.274,71.036) ; R161.1@90.839,103.333 90.838,103.335 91.775,103.335 v1(92.098,103.655) ; R166.1@91.26,101.278 91.498,101.277 v1(91.945,100.833) ; R222.2@91.731,57.222 92.088,57.579 v1(92.555,57.579) ; v1(92.426,79.172) CN17.1@94.358,79.173 ; v1(92.936,56.83) Q1.1@94.023,56.83 ; CN15.1@99.464,84.463 v1(99.464,85.443) ; CN6.48@104.965,120.601 v1(107.058,120.599) ; v1(105.176,80.518) R186.2@106.091,80.518 ; v1(105.255,74.724) R200.2@106.075,74.724 ; v1(105.255,82.725) R184.2@106.075,82.725 ; v1(106.002,105.982) R158.2@106.742,105.983 ; R183.2@106.103,84.074 v1(106.103,84.971) ; R179.2@106.934,95.902 v1(108.463,95.9) ; C50.1@106.934,97.498 v1(107.709,97.498) ; R197.2@106.975,75.867 R197.2@106.978,75.867 v1(107.668,75.867) ; C48.1@60.328,101.087 C46.2@60.328,102.126 ; C46.2@60.328,102.126 60.328,102.128 C46.2@60.455,102.258
  Bottom Layer w0.508: U54.2@87.454,104.189 87.475,104.211 C184.2@89.644,104.211 ; C184.2@89.645,104.21 C184.2@89.644,104.211 ; v1(90.904,104.95) 90.165,104.211 C184.2@89.644,104.211
  other v1: 105.382,61.77 106.271,61.77 83.792,62.405 85.443,62.405 105.382,62.405 106.271,62.405 83.792,63.04 84.808,63.04
VDD1: JP13.3 L3.1 R245.1 T2.4 T4.4 U32.1 U32.24 U32.36 U32.48 | length 25
  Top Layer w0.229: 74.336,50.79 U32.48@75.307,50.792
  Top Layer w0.254: R245.1@64.996,45.832 65.187,45.832 65.728,45.291 U32.24@66.807,45.292 ; v1(73.505,45.006) 73.805,44.707 73.805,43.792 U32.36@73.807,43.79 ; U32.1@73.807,52.292 73.805,52.291 73.805,53.073 v1(74.013,53.282) ; v1(74.14,50.594) 74.336,50.79
  Top Layer w0.508: T4.4@43.076,53.691 43.076,55.09 v1(43.152,55.166) ; v1(53.947,55.166) 53.957,55.156 T2.4@53.957,53.871 ; v1(62.908,45.133) 63.466,45.691 L3.1@63.637,45.691 63.777,45.832 R245.1@64.996,45.832
  L4_SIG w0.508: 54.201,66.746 JP13.3@55.304,66.746 ; 55.303,65.641 JP13.3@55.304,66.746 ; 56.408,66.746 JP13.3@55.304,66.746
  Bottom Layer w0.508: v1(43.152,55.166) v1(53.947,55.166)
  other v1: 64.488,42.847 65.25,42.847 64.488,43.609 65.25,43.609
VDD_ADJ: JP11.3 SB48.2 | length 108.4
  Top Layer w0.508: v1(32.286,12.677) SB48.2@32.287,14.05
  L4_SIG w0.508: v1(32.286,12.677) 34.696,15.088 34.696,26.693 38.1,30.097 38.1,55.603 48.839,66.342 v1(49.502,66.342)
  Bottom Layer w0.508: v1(49.502,66.342) 51.788,66.342 53.312,67.866 53.312,76.274 58.834,81.795 69.078,81.795 71.776,79.097 71.776,70.259 72.413,69.622 JP11.3@73.83,69.622
VDD_MCU: C160.2 C161.2 C162.2 C163.1 C164.2 C165.2 C173.2 C175.2 C176.2 JP6.1 JP13.2 SB43.2 U6.13 U6.31 U6.47 U6.64 U6.79 U6.95 U6.111 U6.128 | length 69.8
  Top Layer w0.203: U6.111@59.083,129.566 59.137,129.511 60.405,129.511 v1(60.909,129.007) ; U6.128@59.083,122.766 59.134,122.715 v1(60.368,122.715) ; v1@60.454,135.097 60.848,135.491 U6.95@60.848,135.966 ; v1(65.1,120.002) 65.301,120.203 U6.13@65.301,120.929 ; v1(66.853,135.098) 67.246,135.491 U6.79@67.246,135.966 ; U6.31@72.528,122.149 72.528,122.475 v1(72.789,122.735) ; v1(72.743,135.166) 72.796,135.219 U6.64@73.49,135.219 ; v1(72.87,128.816) 73.246,128.44 U6.47@73.762,128.44
  Top Layer w0.508: v1(70.203,57.96) 70.711,58.468 78.585,58.468 80.422,56.631 80.422,53.075 81.633,51.864 81.633,48.842 81.252,48.461 81.252,46.403 80.35,45.502 SB43.2@78.74,45.502
  Bottom Layer w0.457: v1(72.743,135.166) C162.2@74.323,135.166
  Bottom Layer w0.508: JP13.2@55.304,69.286 60.551,64.038 60.551,57.452 61.694,56.309 68.552,56.309 v1(70.203,57.96) ; C164.2@58.603,129.216 59.593,129.215 C163.1@59.817,128.992 60.894,128.991 v1(60.909,129.007) ; C173.2@59.083,122.716 v1(60.368,122.715) ; v1(60.452,135.098) C160.2@60.453,136.586 ; v1(65.1,120.002) C175.2@65.1,120.886 ; v1(66.853,135.098) 67.153,135.397 C161.2@67.153,136.566 ; C165.2@72.108,128.77 72.154,128.816 v1(72.87,128.816) ; C176.2@72.789,121.638 v1(72.789,122.735)
VDDA: C167.1 C170.2 L9.2 SB85.1 SB90.2 U6.45 | length 8.8
  Top Layer w0.203: U6.45@74.323,127.566 75.529,127.564 v1(75.664,127.429)
  Bottom Layer w0.508: C170.2@75.41,126.609 C170.2@75.413,126.609 ; SB90.2@77.696,126.38 SB90.2@77.696,126.378 ; SB85.1@77.696,128.58 77.696,128.445 76.807,127.556 75.791,127.556 v1(75.664,127.429) 75.413,127.178 C170.2@75.413,126.609 ; L9.2@79.093,126.578 79.036,126.52 78.895,126.378 SB90.2@77.696,126.378 ; C170.2@75.413,126.609 76.421,126.609 76.426,126.604 77.346,126.604 77.569,126.378 SB90.2@77.696,126.378
VIN_EXT: C123.2 C124.2 C125.2 L4.2 R272.2 U37.1 U37.2 U37.6 | length 34.4
  Top Layer w0.508: 4.536,36.063 L4.2@5.565,36.063 ; 5.565,35.034 L4.2@5.565,36.063 ; 5.565,37.092 L4.2@5.565,36.063 ; 6.594,36.063 L4.2@5.565,36.063 ; 16.604,34.501 C124.2@18.082,34.501 ; 18.082,33.622 C124.2@18.082,34.501 ; 18.082,35.38 C124.2@18.082,34.501 ; 19.561,34.501 C124.2@18.082,34.501 ; C123.2@20.46,34.501 C123.2@21.938,34.501 ; 24.026,33.434 R272.2@24.943,33.434 ; U37.2@26.924,41.736 26.924,43.253 27.196,43.525 v1(27.432,43.525) 27.745,43.525 28.194,43.076 U37.1@28.194,41.736
  Top Layer w0.762: 25.654,35.111 U37.6@25.654,36.986 U37.6@25.654,36.995
  L4_SIG w0.508: 4.536,36.063 L4.2@5.565,36.063 ; 5.565,35.034 L4.2@5.565,36.063 ; 5.565,37.092 L4.2@5.565,36.063 ; 6.594,36.063 L4.2@5.565,36.063
  Bottom Layer w0.508: v1(25.668,33.576) 26.396,33.576 29.359,36.539 29.359,40.366 27.432,42.293 v1(27.432,43.525)
  other v1: 17.117,35.735 17.879,35.735 18.641,35.735 20.673,35.735 21.435,35.735 22.197,35.735 17.117,36.497 17.879,36.497 18.641,36.497 20.673,36.497 21.435,36.497 22.236,36.497
VIN_EXT_CONN: CN25.1 F1.1 | length 21.6
  Top Layer w0.508: 8.771,19.975 CN25.1@10.051,19.975 ; 10.051,17.498 CN25.1@10.051,19.975 ; 10.051,22.454 CN25.1@10.051,19.975 ; 11.328,19.975 CN25.1@10.051,19.975 ; 11.717,15.552 F1.1@13.097,15.554 ; 13.096,13.625 F1.1@13.097,15.554 ; 13.096,17.48 F1.1@13.097,15.554 ; 14.475,15.552 F1.1@13.097,15.554
  L4_SIG w0.508: 8.771,19.975 CN25.1@10.051,19.975 ; 10.051,17.498 CN25.1@10.051,19.975 ; 10.051,22.454 CN25.1@10.051,19.975 ; 11.328,19.975 CN25.1@10.051,19.975
  other v1: 12.443,12.189 13.459,12.215 14.171,12.215 11.732,12.24 12.443,12.85 13.459,12.875 14.171,12.875 11.732,12.901
VIN_EXT_UNFILT: C147.1 F1.2 L4.1 U43.1 | length 21.6
  Top Layer w0.508: 4.536,31.062 L4.1@5.565,31.062 ; 5.565,30.033 L4.1@5.565,31.062 ; 5.565,32.09 L4.1@5.565,31.062 ; 6.594,31.062 L4.1@5.565,31.062 ; 13.647,19.324 U43.1@15.397,19.324 ; 15.397,18.377 U43.1@15.397,19.324 ; 15.397,20.274 U43.1@15.397,19.324 ; 16.319,15.552 F1.2@17.697,15.554 ; 17.145,19.324 U43.1@15.397,19.324 ; 17.696,13.625 F1.2@17.697,15.554 ; 17.696,17.48 F1.2@17.697,15.554 ; 18.844,19.812 C147.1@19.304,19.813 ; 19.075,15.552 F1.2@17.697,15.554 ; 19.304,19.378 C147.1@19.304,19.813 ; 19.761,19.812 C147.1@19.304,19.813
  L4_SIG w0.508: 4.536,31.062 L4.1@5.565,31.062 ; 5.565,30.033 L4.1@5.565,31.062 ; 5.565,32.09 L4.1@5.565,31.062 ; 6.594,31.062 L4.1@5.565,31.062
  other v1: 16.711,12.164 17.422,12.164 18.539,12.164 19.174,12.164 18.539,12.875 16.711,12.901 17.396,12.901 19.174,12.901
VREF: C166.2 C168.2 L8.2 SB86.2 U6.43 U6.44 | length 7.9
  Top Layer w0.203: U6.44@73.609,127.165 73.073,127.165 72.87,126.962 v1(72.87,126.921) 72.969,126.822 74.266,126.822 U6.43@74.323,126.766
  Bottom Layer w0.508: C166.2@71.727,126.881 72.829,126.881 v1(72.87,126.921) 73.182,126.609 73.632,126.609 73.632,128.1 73.977,128.445 73.977,129.644 SB86.2@74.176,129.842
VREF_BIAS: C28.2 C30.2 R111.1 R117.2 R304.1 R305.1 SB22.1 U8.2 | length 41.7
  Top Layer w0.254: v1(112.558,124.076) R111.1@112.558,121.816 ; U8.2@112.959,120.251 U8.2@112.55,120.66 ; C30.2@114.071,121.808 C30.2@114.069,121.808 ; R117.2@116.176,120.107 115.926,119.855 SB22.1@114.77,119.857 114.77,121.107 C30.2@114.069,121.808 ; U8.2@112.55,120.66 R111.1@112.55,121.808 ; U8.2@112.55,120.66 112.547,120.66 112.547,121.808 112.549,121.809 R111.1@112.558,121.816 ; R111.1@112.55,121.808 R111.1@112.558,121.816 ; R111.1@112.55,121.808 C30.2@114.057,121.808 C30.2@114.069,121.808
  Bottom Layer w0.254: v1(112.558,124.076) 112.558,124.242 112.062,124.737 110.132,124.737 109.7,125.169 109.7,132.89 110.589,133.779 110.589,135.049 109.319,136.319 109.319,145.336 109.954,145.971 111.544,145.971 111.798,146.225 111.798,149.273 R304.1@112.682,149.273
VREF_EXT: C179.2 C180.2 Q4.2 R316.2 SB84.1 SB102.1 | length 62.2
  Top Layer w0.381: v1(84.046,113.332) 84.808,112.57 84.808,109.903 85.443,109.268 101.699,109.268 104.43,111.999 107.782,111.999 v1(107.973,112.189)
  L4_SIG w0.381: v1(79.096,127.429) 80.239,126.286 81.76,126.286 82.268,125.778 82.268,120.571 83.157,119.682 83.157,114.221 v1(84.046,113.332)
  Bottom Layer w0.254: R316.2@109.634,121.206 109.573,121.143 109.573,119.494 112.438,119.494 112.433,119.489 Q4.2@112.433,115.534
  Bottom Layer w0.381: SB84.1@79.093,128.58 79.096,128.58 v1(79.096,127.429) ; v1(107.973,112.189) 109.573,112.189 110.462,113.078 110.462,115.153 110.843,115.534 Q4.2@112.433,115.534
VSENSE: C185.2 R244.1 R323.2 SB29.1 | length 119.7
  Top Layer w0.127: R244.1@13.652,46.421 v1(14.323,46.421) ; v1(59.662,107.427) 59.911,107.427 60.198,107.713 62.641,110.157 68.984,110.157 71.178,112.352 SB29.1@71.179,113.652
  Bottom Layer w0.127: v1(14.323,46.421) 13.625,47.12 13.625,49.642 16.609,52.626 23.213,52.626 35.634,65.047 35.634,85.976 34.262,87.348 34.262,94.155 32.738,95.679 32.738,104.823 34.138,106.223 34.138,108.737 35.024,109.624 41.222,109.624 42.108,108.737 46.35,108.737 46.835,108.252 58.519,108.252 59.345,107.427 v1(59.662,107.427)
pads on no net: B1.NPTH1 B1.NPTH2 CN1.2 CN1.6 CN5.NPTH1 CN5.NPTH2 CN6.NPTH1 CN6.NPTH2 CN11.1 CN11.7 CN13.NPTH1 CN13.NPTH2 CN15.7 CN15.11 CN15.12 CN15.13 CN16.0 CN16.1 CN16.2 CN16.9 CN17.0 CN17.7 CN19.0 CN20.4 CN20.5 CN20.6 CN21.4 CN22.PTH1 CN22.PTH2 CN22.PTH3 CN22.PTH4 CN22.PTH5 CN22.PTH6 CN23.2 CN23.5 CN23.7 CN23.MT1 CN23.MT2 CN26.2 CN26.5 CN26.7 CN26.MT1 CN26.MT2 CN28.1 CN28.8 CN28.NPTH1 CN28.NPTH2 CN31.C6 CN31.NPTH1 CN31.NPTH2 H3.1 H4.1 LPB1.NPTH1 LPB1.NPTH2 SW2.10 SW2.11 SW2.12 SW2.PTH1 SW2.PTH2 SW3.10 SW3.11 SW3.12 SW3.PTH1 SW3.PTH2 SW5.10 SW5.11 SW5.12 SW5.PTH1 SW5.PTH2 SW6.10 SW6.11 SW6.12 SW6.PTH1 SW6.PTH2 U1.5 U6.NPTH1 U6.NPTH2 U6.NPTH3 U6.NPTH4 U6.NPTH5 U6.NPTH6 U11.E3 U12.3 U12.11 U17.4 U17.8 U17.9 U17.11 U17.12 U17.14 U17.15 U17.18 U17.19 U17.21 U20.5 U26.6 U31.4 U32.10 U32.12 U32.13 U32.27 U32.38 U35.A6 U35.A8 U35.A9 U35.B4 U35.B5 U35.B8 U35.B9 U35.C4 U35.C5 U35.C6 U35.C7 U35.C8 U35.E1 U35.E5 U35.F4 U35.F5 U35.F6 U35.F8 U35.F9 U35.G4 U35.H2 U35.H3 U35.H4 U35.H5 U37.5 U40.A1 U40.A2 U40.A3 U40.A4 U40.A5 U40.A6 U40.A8 U40.A9 U40.A10 U40.A11 U40.A12 U40.A13 U40.B1 U40.B2 U40.B3 U40.B4 U40.B5 U40.B6 U40.B7 U40.B8 U40.B9 U40.B10 U40.B11 U40.B12 U40.B13 U40.B14 U40.B15 U40.C2 U40.C3 U40.C4 U40.C11 U40.C12 U40.C13 U40.C14 U40.C15 U40.D1 U40.D2 U40.D3 U40.D4 U40.D10 U40.D11 U40.D13 U40.D14 U40.E1 U40.E2 U40.E3 U40.E4 U40.E12 U40.E13 U40.E14 U40.E15 U40.F1 U40.F4 U40.F14 U40.G4 U40.G14 U40.G15 U40.H1 U40.H2 U40.H3 U40.H4 U40.H14 U40.H15 U40.J2 U40.J3 U40.J4 U40.K1 U40.K2 U40.K3 U40.K12 U40.K14 U40.K15 U40.L1 U40.L3 U40.L12 U40.L13 U40.L14 U40.L15 U40.M2 U40.M3 U40.M4 U40.M5 U40.M6 U40.M7 U40.M12 U40.M13 U40.M14 U40.M15 U40.N2 U40.N4 U40.N5 U40.N6 U40.N7 U40.N11 U40.N13 U40.N14 U40.N15 U40.P2 U40.P4 U40.P5 U40.P6 U40.P7 U40.P8 U40.P9 U40.P10 U40.P11 U40.P12 U40.P13 U40.P14 U40.P15 U40.R2 U40.R3 U40.R6 U40.R7 U40.R8 U40.R9 U40.R10 U40.R11 U40.R12 U40.R13 U42.10 U42.25 U45.4 U45.5 U47.3 U53.1 U53.2 U54.3 U54.4 U54.5 U54.6 U54.11 U54.12 U54.13 U54.14 U55.5 X2.2 X2.4
copper on no net:
  other v1: 9.751,51.864 9.243,53.896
